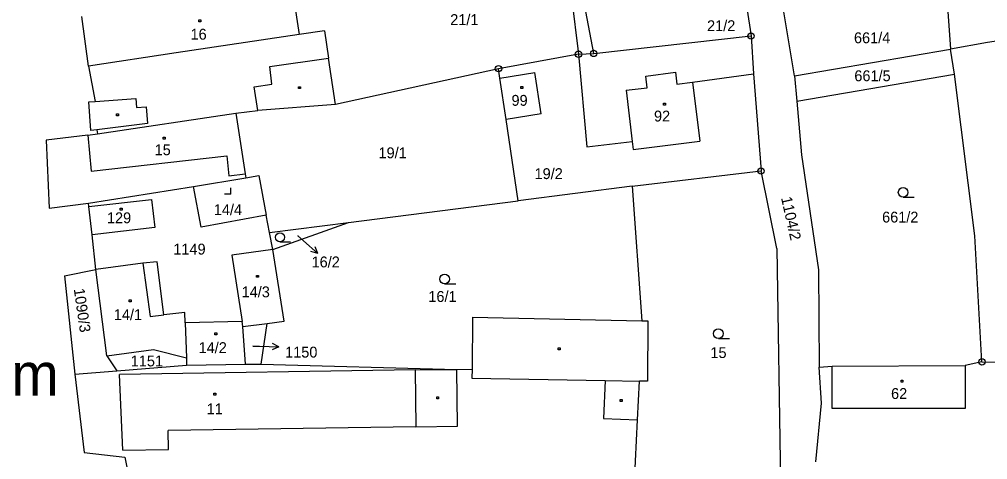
# Model space of a CAD drawing. Extents: x -794142 to -791199, y -1109267 to -1105626.
# Drawn here: x -793464.4 to -793312.7, y -1107745.8 to -1107676.8 of the extents above; entities that cross this region are included whole.
import ezdxf

# ---------------------------------------------------------------- set-up
doc = ezdxf.new("R2010")
doc.units = 0
for name, color, linetype in [('Komunikace', 7, 'Continuous'), ('Vrstva 1', 7, 'Continuous'), ('Vrstva 14', 7, 'Continuous'), ('Vrstva 15', 7, 'Continuous'), ('Vrstva 16', 7, 'Continuous'), ('Vrstva 2', 7, 'Continuous'), ('Vrstva 23', 7, 'Continuous'), ('Vrstva 25', 7, 'Continuous'), ('Vrstva 28', 7, 'Continuous'), ('Vrstva 35', 7, 'Continuous')]:
    doc.layers.add(name, color=color, linetype=linetype)

msp = doc.modelspace()

# ---------------------------------------------------------------- linework, layer by layer
at = {"layer": 'Komunikace'}
for p, q in [((-793420.78, -1107710.72), (-793419.9, -1107711.49)), ((-793427.82, -1107727.99), (-793426.78, -1107728.02))]:
    msp.add_line(p, q, dxfattribs=at)
at = {"layer": 'Vrstva 1'}
for p, q in [((-793353.19, -1107657.31), (-793349.77, -1107679.43)), ((-793374.43, -1107682.16), (-793378.14, -1107662.48)), ((-793378.19, -1107671.12), (-793376.81, -1107682.29)), ((-793319.26, -1107671.37), (-793318.5, -1107681.47)), ((-793421.77, -1107671.56), (-793420.56, -1107679.22)), ((-793342.97, -1107685.65), (-793344.69, -1107675.35)), ((-793453.57, -1107684.14), (-793454.66, -1107676.39)), ((-793287.74, -1107676.37), (-793312.7, -1107680.47)), ((-793416.63, -1107678.64), (-793420.56, -1107679.22)), ((-793416.63, -1107678.64), (-793415.99, -1107682.92)), ((-793374.43, -1107682.16), (-793349.77, -1107679.43)), ((-793349.77, -1107679.43), (-793349.37, -1107685.33)), ((-793312.7, -1107680.47), (-793318.5, -1107681.47)), ((-793342.97, -1107685.65), (-793318.5, -1107681.47)), ((-793317.88, -1107685.42), (-793318.5, -1107681.47)), ((-793414.91, -1107690.16), (-793415.99, -1107682.92)), ((-793376.81, -1107682.29), (-793389.34, -1107684.55)), ((-793376.81, -1107682.29), (-793374.43, -1107682.16)), ((-793376.81, -1107682.29), (-793375.49, -1107696.79)), ((-793453.57, -1107684.14), (-793452.56, -1107689.68)), ((-793389.34, -1107684.55), (-793414.91, -1107690.16)), ((-793389.12, -1107686.04), (-793389.34, -1107684.55)), ((-793389.12, -1107686.04), (-793383.66, -1107685.14)), ((-793382.68, -1107691.64), (-793383.66, -1107685.14)), ((-793388.15, -1107692.52), (-793389.12, -1107686.04)), ((-793358.93, -1107686.65), (-793349.37, -1107685.33)), ((-793358.93, -1107686.65), (-793357.79, -1107695.9)), ((-793349.37, -1107685.33), (-793348.2, -1107700.57)), ((-793342.97, -1107685.65), (-793342.62, -1107689.63)), ((-793342.62, -1107689.63), (-793317.88, -1107685.42)), ((-793314.69, -1107710.71), (-793317.88, -1107685.42)), ((-793453.56, -1107689.75), (-793452.56, -1107689.68)), ((-793342.62, -1107689.63), (-793341.88, -1107698.06)), ((-793453.23, -1107694.24), (-793453.56, -1107689.75)), ((-793430.48, -1107691.52), (-793427.07, -1107691.12)), ((-793414.91, -1107690.16), (-793427.07, -1107691.12)), ((-793452.18, -1107694.75), (-793430.48, -1107691.52)), ((-793430.48, -1107691.52), (-793429.04, -1107701.01)), ((-793382.68, -1107691.64), (-793388.15, -1107692.52)), ((-793386.26, -1107705.24), (-793388.15, -1107692.52)), ((-793452.29, -1107694.13), (-793453.23, -1107694.24)), ((-793452.29, -1107694.13), (-793452.18, -1107694.75)), ((-793453.71, -1107694.95), (-793460.23, -1107695.76)), ((-793460.23, -1107695.76), (-793459.78, -1107706.39)), ((-793453.71, -1107694.95), (-793452.18, -1107694.75)), ((-793375.49, -1107696.79), (-793368.39, -1107695.98)), ((-793368.39, -1107695.98), (-793368.24, -1107697.23)), ((-793368.24, -1107697.23), (-793357.79, -1107695.9)), ((-793341.88, -1107698.06), (-793339.21, -1107716.05)), ((-793437.14, -1107702.98), (-793428.95, -1107701.63)), ((-793429.04, -1107701.01), (-793428.95, -1107701.63)), ((-793428.95, -1107701.63), (-793426.88, -1107701.28)), ((-793426.88, -1107701.28), (-793425.75, -1107707.48)), ((-793368.42, -1107702.97), (-793348.2, -1107700.57)), ((-793345.71, -1107712.69), (-793348.2, -1107700.57)), ((-793453.61, -1107705.6), (-793437.14, -1107702.98)), ((-793435.93, -1107709.36), (-793437.14, -1107702.98)), ((-793368.42, -1107702.97), (-793386.26, -1107705.24)), ((-793368.42, -1107702.97), (-793366.9, -1107724.02)), ((-793459.78, -1107706.39), (-793453.61, -1107705.6)), ((-793453.55, -1107706.16), (-793453.61, -1107705.6)), ((-793453.04, -1107710.55), (-793453.55, -1107706.16)), ((-793412.84, -1107708.62), (-793386.26, -1107705.24)), ((-793425.75, -1107707.48), (-793435.93, -1107709.36)), ((-793425.21, -1107710.19), (-793425.75, -1107707.48)), ((-793425.21, -1107710.19), (-793412.84, -1107708.62)), ((-793424.68, -1107712.87), (-793412.84, -1107708.62)), ((-793452.43, -1107715.98), (-793453.04, -1107710.55)), ((-793424.68, -1107712.87), (-793425.21, -1107710.19)), ((-793313.58, -1107730.47), (-793314.69, -1107710.71)), ((-793424.68, -1107712.87), (-793431.11, -1107713.74)), ((-793431.11, -1107713.74), (-793429.53, -1107724.17)), ((-793422.91, -1107724.09), (-793424.68, -1107712.87)), ((-793345.71, -1107712.69), (-793345.12, -1107750.73)), ((-793445.1, -1107715.03), (-793452.43, -1107715.98)), ((-793442.81, -1107714.8), (-793445.1, -1107715.03)), ((-793441.78, -1107723.11), (-793442.81, -1107714.8)), ((-793457.35, -1107717.01), (-793452.43, -1107715.98)), ((-793450.74, -1107729.51), (-793452.43, -1107715.98)), ((-793339.21, -1107716.05), (-793339.07, -1107731.3)), ((-793457.35, -1107717.01), (-793455.75, -1107732.4)), ((-793438.47, -1107722.72), (-793441.78, -1107723.11)), ((-793438.45, -1107724.36), (-793438.47, -1107722.72)), ((-793429.53, -1107724.17), (-793438.45, -1107724.36)), ((-793438.45, -1107724.36), (-793438.26, -1107729.84)), ((-793429.41, -1107724.95), (-793429.53, -1107724.17)), ((-793429.41, -1107724.95), (-793425.61, -1107724.45)), ((-793426.54, -1107730.81), (-793425.61, -1107724.45)), ((-793425.61, -1107724.45), (-793422.91, -1107724.09)), ((-793393.41, -1107723.47), (-793393.49, -1107731.64)), ((-793393.41, -1107723.47), (-793366.9, -1107724.02)), ((-793366.9, -1107724.02), (-793365.92, -1107724.04)), ((-793365.92, -1107724.04), (-793366.02, -1107733.52)), ((-793429, -1107730.84), (-793429.41, -1107724.95)), ((-793450.74, -1107729.51), (-793443.39, -1107728.56)), ((-793443.39, -1107728.56), (-793438.26, -1107729.84)), ((-793450.74, -1107729.51), (-793449.13, -1107731.87)), ((-793438.26, -1107729.84), (-793438.22, -1107731.01)), ((-793313.58, -1107730.47), (-793316.2, -1107731.05)), ((-793313.58, -1107730.47), (-793309.46, -1107730.53)), ((-793455.75, -1107732.4), (-793449.13, -1107731.87)), ((-793449.13, -1107731.87), (-793438.22, -1107731.01)), ((-793438.22, -1107731.01), (-793429, -1107730.84)), ((-793429, -1107730.84), (-793426.54, -1107730.81)), ((-793426.54, -1107730.81), (-793395.89, -1107731.66)), ((-793395.89, -1107731.66), (-793393.49, -1107731.64)), ((-793339.07, -1107731.3), (-793337.05, -1107731.17)), ((-793338.75, -1107736.94), (-793339.07, -1107731.3)), ((-793337.05, -1107731.17), (-793316.2, -1107731.05)), ((-793455.75, -1107732.4), (-793454.29, -1107744.65)), ((-793367.55, -1107739.54), (-793367.26, -1107733.5)), ((-793366.02, -1107733.52), (-793367.26, -1107733.5)), ((-793339.62, -1107746.13), (-793338.75, -1107736.94)), ((-793368.19, -1107752.55), (-793367.55, -1107739.54)), ((-793454.29, -1107744.65), (-793447.91, -1107745.39)), ((-793447.91, -1107745.39), (-793445.71, -1107756.16))]:
    msp.add_line(p, q, dxfattribs=at)
msp.add_lwpolyline([(-793453.55, -1107706.16), (-793443.73, -1107705.02), (-793443.22, -1107709.43), (-793453.04, -1107710.55)], dxfattribs=at)
at = {"layer": 'Vrstva 16'}
for p, q in [((-793419.9, -1107711.49), (-793417.653, -1107713.477)), ((-793417.653, -1107713.477), (-793418.07, -1107712.44)), ((-793417.653, -1107713.477), (-793418.733, -1107713.189)), ((-793423.781, -1107728.101), (-793424.767, -1107727.574)), ((-793426.78, -1107728.02), (-793423.781, -1107728.101)), ((-793423.781, -1107728.101), (-793424.794, -1107728.574))]:
    msp.add_line(p, q, dxfattribs=at)
at = {"layer": 'Vrstva 2'}
for p, q in [((-793420.56, -1107679.22), (-793439.85, -1107682.07)), ((-793439.85, -1107682.07), (-793453.57, -1107684.14)), ((-793425.19, -1107684.23), (-793415.99, -1107682.92)), ((-793424.88, -1107686.96), (-793425.19, -1107684.23)), ((-793366.28, -1107685.72), (-793361.6, -1107685.12)), ((-793361.6, -1107685.12), (-793361.38, -1107686.95)), ((-793366.06, -1107687.53), (-793366.28, -1107685.72)), ((-793361.38, -1107686.95), (-793358.93, -1107686.65)), ((-793427.62, -1107687.4), (-793424.88, -1107686.96)), ((-793427.07, -1107691.12), (-793427.62, -1107687.4)), ((-793369.36, -1107687.93), (-793366.06, -1107687.53)), ((-793369.36, -1107687.93), (-793368.39, -1107695.98)), ((-793452.56, -1107689.68), (-793446.18, -1107689.21)), ((-793446.18, -1107689.21), (-793446.08, -1107690.61)), ((-793446.08, -1107690.61), (-793444.53, -1107690.51)), ((-793444.53, -1107690.51), (-793444.33, -1107693.16)), ((-793444.33, -1107693.16), (-793452.29, -1107694.13)), ((-793453.71, -1107694.95), (-793453.17, -1107700.61)), ((-793453.17, -1107700.61), (-793431.91, -1107698.19)), ((-793431.91, -1107698.19), (-793431.59, -1107701.32)), ((-793431.59, -1107701.32), (-793429.04, -1107701.01)), ((-793445.1, -1107715.03), (-793443.95, -1107723.37)), ((-793443.95, -1107723.37), (-793441.78, -1107723.11)), ((-793402.39, -1107731.7), (-793448.74, -1107732.44)), ((-793402.39, -1107731.7), (-793395.89, -1107731.66)), ((-793402.39, -1107731.7), (-793402.28, -1107740.63)), ((-793395.78, -1107740.55), (-793395.89, -1107731.66)), ((-793393.49, -1107731.64), (-793393.5, -1107733.01)), ((-793337.04, -1107737.8), (-793337.05, -1107731.17)), ((-793316.2, -1107731.05), (-793316.24, -1107737.76)), ((-793448.23, -1107744.31), (-793448.74, -1107732.44)), ((-793393.5, -1107733.01), (-793372.61, -1107733.4)), ((-793372.61, -1107733.4), (-793372.88, -1107739.32)), ((-793372.61, -1107733.4), (-793367.26, -1107733.5)), ((-793316.24, -1107737.76), (-793337.04, -1107737.8)), ((-793372.88, -1107739.32), (-793367.55, -1107739.54)), ((-793402.28, -1107740.63), (-793441.11, -1107741.24)), ((-793441.07, -1107744.18), (-793441.11, -1107741.24)), ((-793402.28, -1107740.63), (-793395.78, -1107740.55)), ((-793448.23, -1107744.31), (-793441.07, -1107744.18))]:
    msp.add_line(p, q, dxfattribs=at)
at = {"layer": 'Vrstva 23'}
for p, q in [((-793431.28, -1107704.23), (-793431.28, -1107703.23)), ((-793431.28, -1107704.23), (-793432.28, -1107704.23)), ((-793325.94, -1107704.67), (-793324.19, -1107704.67)), ((-793423.59, -1107711.67), (-793421.927, -1107711.67)), ((-793397.79, -1107718.25), (-793396.04, -1107718.25)), ((-793354.89, -1107726.8), (-793353.14, -1107726.8))]:
    msp.add_line(p, q, dxfattribs=at)
for centre, radius in [((-793325.94, -1107703.92), 0.75), ((-793423.59, -1107710.958), 0.712), ((-793397.79, -1107717.5), 0.75), ((-793354.89, -1107726.05), 0.75)]:
    msp.add_circle(centre, radius, dxfattribs=at)
at = {"layer": 'Vrstva 25'}
for p, q in [((-793436.29, -1107676.9), (-793435.99, -1107676.9)), ((-793436.29, -1107677.2), (-793436.29, -1107676.9)), ((-793435.99, -1107677.2), (-793436.29, -1107677.2)), ((-793435.99, -1107676.9), (-793435.99, -1107677.2)), ((-793420.66, -1107687.37), (-793420.36, -1107687.37)), ((-793420.66, -1107687.67), (-793420.66, -1107687.37)), ((-793420.36, -1107687.67), (-793420.66, -1107687.67)), ((-793420.36, -1107687.37), (-793420.36, -1107687.67)), ((-793385.83, -1107687.34), (-793385.53, -1107687.34)), ((-793385.83, -1107687.64), (-793385.83, -1107687.34)), ((-793385.53, -1107687.64), (-793385.83, -1107687.64)), ((-793385.53, -1107687.34), (-793385.53, -1107687.64)), ((-793363.48, -1107689.96), (-793363.18, -1107689.96)), ((-793363.48, -1107690.26), (-793363.48, -1107689.96)), ((-793363.18, -1107690.26), (-793363.48, -1107690.26)), ((-793363.18, -1107689.96), (-793363.18, -1107690.26)), ((-793449.21, -1107691.63), (-793448.91, -1107691.63)), ((-793449.21, -1107691.93), (-793449.21, -1107691.63)), ((-793448.91, -1107691.93), (-793449.21, -1107691.93)), ((-793448.91, -1107691.63), (-793448.91, -1107691.93)), ((-793441.87, -1107695.27), (-793441.57, -1107695.27)), ((-793441.87, -1107695.57), (-793441.87, -1107695.27)), ((-793441.57, -1107695.57), (-793441.87, -1107695.57)), ((-793441.57, -1107695.27), (-793441.57, -1107695.57)), ((-793448.61, -1107706.4), (-793448.31, -1107706.4)), ((-793448.61, -1107706.7), (-793448.61, -1107706.4)), ((-793448.31, -1107706.7), (-793448.61, -1107706.7)), ((-793448.31, -1107706.4), (-793448.31, -1107706.7)), ((-793427.26, -1107716.93), (-793426.96, -1107716.93)), ((-793427.26, -1107717.23), (-793427.26, -1107716.93)), ((-793426.96, -1107716.93), (-793426.96, -1107717.23)), ((-793426.96, -1107717.23), (-793427.26, -1107717.23)), ((-793447.21, -1107720.75), (-793446.91, -1107720.75)), ((-793447.21, -1107721.05), (-793447.21, -1107720.75)), ((-793446.91, -1107721.05), (-793447.21, -1107721.05)), ((-793446.91, -1107720.75), (-793446.91, -1107721.05)), ((-793433.77, -1107725.94), (-793433.47, -1107725.94)), ((-793433.77, -1107726.24), (-793433.77, -1107725.94)), ((-793433.47, -1107725.94), (-793433.47, -1107726.24)), ((-793433.47, -1107726.24), (-793433.77, -1107726.24)), ((-793379.97, -1107728.28), (-793379.67, -1107728.28)), ((-793379.97, -1107728.58), (-793379.97, -1107728.28)), ((-793379.67, -1107728.58), (-793379.97, -1107728.58)), ((-793379.67, -1107728.28), (-793379.67, -1107728.58)), ((-793326.27, -1107733.33), (-793325.97, -1107733.33)), ((-793326.27, -1107733.63), (-793326.27, -1107733.33)), ((-793325.97, -1107733.63), (-793326.27, -1107733.63)), ((-793325.97, -1107733.33), (-793325.97, -1107733.63)), ((-793433.96, -1107735.4), (-793433.66, -1107735.4)), ((-793433.96, -1107735.7), (-793433.96, -1107735.4)), ((-793433.66, -1107735.7), (-793433.96, -1107735.7)), ((-793433.66, -1107735.4), (-793433.66, -1107735.7)), ((-793399.02, -1107735.95), (-793398.72, -1107735.95)), ((-793399.02, -1107736.25), (-793399.02, -1107735.95)), ((-793398.72, -1107736.25), (-793399.02, -1107736.25)), ((-793398.72, -1107735.95), (-793398.72, -1107736.25)), ((-793370.29, -1107736.36), (-793369.99, -1107736.36)), ((-793370.29, -1107736.66), (-793370.29, -1107736.36)), ((-793369.99, -1107736.66), (-793370.29, -1107736.66)), ((-793369.99, -1107736.36), (-793369.99, -1107736.66))]:
    msp.add_line(p, q, dxfattribs=at)
at = {"layer": 'Vrstva 28'}
for centre, radius in [((-793349.77, -1107679.43), 0.5), ((-793349.77, -1107679.43), 0.01), ((-793376.81, -1107682.29), 0.5), ((-793374.43, -1107682.16), 0.5), ((-793376.81, -1107682.29), 0.01), ((-793374.43, -1107682.16), 0.01), ((-793389.34, -1107684.55), 0.5), ((-793389.34, -1107684.55), 0.01), ((-793348.2, -1107700.57), 0.5), ((-793348.2, -1107700.57), 0.01), ((-793313.58, -1107730.47), 0.5), ((-793313.58, -1107730.47), 0.01)]:
    msp.add_circle(centre, radius, dxfattribs=at)

# ---------------------------------------------------------------- texts
at = {"layer": 'Vrstva 14'}
for s, height, p in [('21/1', 1.7, (-793396.906, -1107677.71)), ('21/2', 1.7, (-793356.663, -1107678.67)), ('661/4', 1.7, (-793333.639, -1107680.56)), ('661/5', 1.7, (-793333.58, -1107686.51)), ('19/1', 1.7, (-793408.147, -1107698.58)), ('19/2', 1.7, (-793383.693, -1107701.84)), ('661/2', 1.7, (-793329.233, -1107708.65)), ('16/2', 0.1, (-793420.927, -1107710.72)), ('1149', 1.7, (-793440.299, -1107713.66)), ('16/1', 1.7, (-793400.337, -1107721.08)), ('1150', 0.1, (-793427.967, -1107727.99)), ('15', 1.7, (-793356.136, -1107729.87)), ('1151', 1.7, (-793446.973, -1107731.18))]:
    msp.add_text(s, height=height, dxfattribs=at).set_placement(p)
for s, rotation, p in [('1104/2', 282.69081, (-793345.082, -1107704.779)), ('1090/3', 278.22348, (-793455.905, -1107719.069))]:
    msp.add_text(s, height=1.7, rotation=rotation, dxfattribs=at).set_placement(p)
at = {"layer": 'Vrstva 15'}
for s, p in [('16', (-793437.6, -1107680)), ('99', (-793387.307, -1107690.36)), ('92', (-793364.977, -1107692.82)), ('15', (-793443.226, -1107698.1)), ('14/4', (-793433.955, -1107707.48)), ('129', (-793450.7, -1107708.76)), ('14/3', (-793429.599, -1107720.36)), ('14/1', (-793449.622, -1107723.92)), ('14/2', (-793436.339, -1107729.09)), ('62', (-793327.827, -1107736.28)), ('11', (-793435.073, -1107738.68))]:
    msp.add_text(s, height=1.7, dxfattribs=at).set_placement(p)
at = {"layer": 'Vrstva 16'}
for s, p in [('16/2', (-793418.633, -1107715.67)), ('1150', (-793422.78, -1107729.8))]:
    msp.add_text(s, height=1.7, dxfattribs=at).set_placement(p)
at = {"layer": 'Vrstva 35'}
msp.add_text('Chlum', height=6.7, dxfattribs=at).set_placement((-793484.12, -1107735.78))

doc.saveas('drawing.dxf')
